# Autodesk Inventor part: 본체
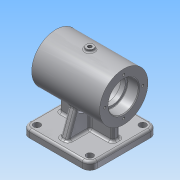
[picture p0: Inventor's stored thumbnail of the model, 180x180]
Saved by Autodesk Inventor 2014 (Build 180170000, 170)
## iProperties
Created: 2019-06
Part Number: 본체
Material: 알루미늄 6061
Document SubType Name: Modeling
Designer: user
Density: 2.71 g/cm^3
Appearance: 알루미늄 - 평지
Mass: 688.176 g
Surface Area: 608.027 cm^2
Volume: 253.94 cm^3
Author: user
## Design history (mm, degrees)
sketch "스케치1"
  geometry: L1 (-45, 0)-(45, 0); L2 (-45, 0)-(-45, 32); L3 (-45, 32)-(45, 32); L4 (45, 32)-(45, 0); L5 (-45, 20)-(-30, 20); L6 (-30, 20)-(-30, 17); L7 (-30, 17)-(-24, 17); L8 (-24, 17)-(-24, 25); L9 (-24, 25)-(24, 25); L10 (24, 25)-(24, 17); L11 (24, 17)-(30, 17); L12 (30, 17)-(30, 20); L13 (30, 20)-(45, 20); 2 further points
  constraints: 26 end point, 7 parallel, 4 perpendicular, 2 point on line, 1 coincident, 1 collinear, 1 horizontal, 1 midpoint
  dimensions: "d0" = 90 distance of L1.end L1.start; "d1" = 64 diameter of L3 L1; "d2" = 34 diameter of L7 L1; "d3" = 40 diameter of L5 L1; "d4" = 34 diameter of L11 L1; "d5" = 40 diameter of L13 L1; "d6" = 50 diameter of L9 L1; "d7" = 48 distance between parallel lines of L10 L8; "d8" = 15 distance between parallel lines of L6 L2; "d9" = 15 distance between parallel lines of L4 L12; "d10" = 6 distance between parallel lines of L8 L6; "d11" = 6 distance between parallel lines of L12 L10 (derived)
revolve "회전1" sketch "스케치1" stored, may be unused: angle "d12" = 90 deg
sketch "스케치2"
  geometry: L1 (-45, -55)-(45, -55); L2 (45, -55)-(45, -65); L3 (45, -65)-(-45, -65); L4 (-45, -65)-(-45, -55); 2 further points
  constraints: 8 end point, 2 parallel, 1 horizontal, 1 midpoint, 1 perpendicular, 1 vertical alignment
  dimensions: "d13" = 10 distance between parallel lines of L1 L3; "d14" = 90 distance between parallel lines of L2 L4; "d15" = 65 distance from line of L3 point (0, 0)
extrude "돌출1" join sketch "스케치2" stored distance "d16" = 90; taper "d17" = 0 deg
sketch "스케치3"
  geometry: L1 (40, -40)-(50, -40); L2 (50, -40)-(50, -50); L3 (50, -50)-(40, -50); L4 (40, -50)-(40, -40); L5 (40, -40)-(50, -50); L6 (50, -40)-(40, -50); 1 further point
  constraints: 12 end point, 2 midpoint, 2 parallel, 1 horizontal, 1 perpendicular
  dimensions: "d18" = 10 distance of L2.end L3.end; "d19" = 10 distance of L1.end L2.end
extrude "돌출2" join sketch "스케치3" stored distance "d20" = 90; taper "d21" = 0 deg
sketch "스케치4"
  geometry: L1 (24, 25)-(-24, 25) reference; L2 (-24, 25)-(-24, 17) reference; L3 (-24, 17)-(-30, 17) reference; L4 (-30, 17)-(-30, 20) reference; L5 (-30, 20)-(-45, 20) reference; L6 (-45, 20)-(-45, 32) reference; L7 (-45, 32)-(45, 32) reference; L8 (45, 32)-(45, 20) reference; L9 (45, 20)-(30, 20) reference; L10 (30, 20)-(30, 17) reference; L11 (30, 17)-(24, 17) reference; L12 (24, 17)-(24, 25) reference; L13 (-24, -25)-(24, -25) reference; L14 (24, -25)-(24, -17) reference; L15 (24, -17)-(30, -17) reference; L16 (30, -17)-(30, -20) reference; L17 (30, -20)-(45, -20) reference; L18 (45, -20)-(45, -32) reference; L19 (45, -32)-(5, -32) reference; L20 (5, -32)-(5, -55) reference; L21 (5, -55)-(45, -55) reference; L22 (45, -55)-(45, -65) reference; L23 (45, -65)-(-45, -65) reference; L24 (-45, -65)-(-45, -55) reference; L25 (-45, -55)-(-5, -55) reference; L26 (-5, -55)-(-5, -32) reference; L27 (-5, -32)-(-45, -32) reference; L28 (-45, -32)-(-45, -20) reference; L29 (-45, -20)-(-30, -20) reference; L30 (-30, -20)-(-30, -17) reference; L31 (-30, -17)-(-24, -17) reference; L32 (-24, -17)-(-24, -25) reference; L33 (-35, -32)-(-35, -55); L34 (35, -32)-(35, -55); 1 further point
  constraints: 4 end point, 4 point on line, 2 parallel
  dimensions: "d22" = 35 distance from line of L33 point (0, 0); "d23" = 35 distance from line of L34 point (0, 0)
feature "리브1" sketch "스케치4" dims "d24" = 1, "d25" = 10, "d26" = 0, "d27" = 0, "d28" = 1, "d29" = 1
sketch "스케치5"
  geometry: L1 (-45, -55)-(-5, -55) reference; L2 (-5, -55)-(-5, -31.607) reference; L3 (5, -31.607)-(5, -55) reference; L4 (5, -55)-(45, -55) reference; L5 (45, -55)-(45, -65) reference; L6 (45, -65)-(-45, -65) reference; L7 (-45, -65)-(-45, -55) reference; L8 (-23.058, -22.189)-(-35, -55); L9 (23.058, -22.189)-(35, -55); C1 r 25 at (0, 0) reference; A1 r 32 centre (0, 0) between (5, -31.607) and (-5, -31.607) reference; 1 further point
  constraints: 4 end point, 2 point on circle, 2 point on line
  dimensions: "d30" = 10 distance from line of L7 L8.end; "d31" = 10 distance from line of L5 L9.end; "d32" = 110 deg angle of L1 L8; "d33" = 110 deg angle of L4 L9
feature "리브2" sketch "스케치5" dims "d34" = 1, "d35" = 10, "d36" = 0, "d37" = 0, "d38" = 1, "d39" = 1
fillet "모깎기1" dims "d40" = 10
sketch "스케치6"
  geometry: L1 (-5, -5)-(75, -85); L2 (75, -5)-(-5, -85); C1 r 4.5 at (0, -10); C2 r 4.5 at (0, -80); C3 r 4.5 at (70, -10); C4 r 4.5 at (70, -80); A1 r 10 centre (70, -80) between (70, -90) and (80, -80) reference; A2 r 10 centre (70, -10) between (80, -10) and (70, 0) reference; A3 r 10 centre (0, -10) between (0, 0) and (-10, -10) reference; A4 r 10 centre (0, -80) between (-10, -80) and (0, -90) reference; 1 further point
  constraints: 4 centre point, 4 coincident, 4 end point, 2 midpoint
  dimensions: "d42" = 9 diameter of C1; "d43" = 9 diameter of C2; "d44" = 9 diameter of C3; "d45" = 9 diameter of C4
extrude "돌출3" cut sketch "스케치6" stored distance "d52" = 90; taper "d53" = 0 deg
chamfer "모따기1" distance "d61" = 1; stored, may be unused: second distance "d62" = 2, angle "d63" = 45 deg
fillet "모깎기2" dims "d64" = 3
fillet "모깎기3" dims "d65" = 0.6
node "작업 평면1"
sketch "스케치9"
  geometry: C1 r 5 at (0, 0); 1 further point
  constraints: 1 centre point, 1 coincident
  dimensions: "d67" = 10 diameter of C1
extrude "돌출4" join sketch "스케치9" stored distance "d68" = 5; taper "d69" = 0 deg
sketch "스케치10"
  geometry: C1 r 5 at (0, 0) reference; 1 further point
  constraints: 1 coincident
hole "구멍1" sketch "스케치10" at (0, 0) diameter "d70" = 4.917; stored, may be unused: countersink angle "d74" = 90 deg, drill point angle "d76" = 118 deg; dims "d71" = 6, "d72" = 4, "d73" = 2, "d75" = 8
fillet "모깎기4" dims "d77" = 3
fillet "모깎기5" dims "d78" = 3
fillet "모깎기6" dims "d79" = 3
fillet "모깎기7" dims "d80" = 3
sketch "스케치11"
  geometry: L1 (0, 0)-(25, 0); C1 r 21 at (0, 0) reference; 1 further point
  constraints: 2 end point, 1 coincident, 1 horizontal
  dimensions: "d81" = 25 distance of L1.start L1.end
hole "구멍2" sketch "스케치11" at (25, 0) diameter "d82" = 3.242; stored, may be unused: countersink angle "d86" = 90 deg, drill point angle "d88" = 118 deg; dims "d83" = 7, "d84" = 4, "d85" = 2, "d87" = 9
sketch "스케치12"
  geometry: L1 (35, 65)-(-35, 65) reference; L2 (45, 58)-(45, 65) reference; 2 further points
  constraints: 1 other
  dimensions: "d92" = 45 distance from line of L2 point (0, 61); "d93" = 4 distance from line of point (0, 61) L1
feature "엠보싱1" sketch "스케치12" dims "d13" = 10, "d94" = 0.5, "d95" = 0
fillet "모깎기8" dims "d96" = 2
sketch "스케치14"
  geometry: L1 (0, 0)-(70, 0) reference; L2 (10, -5)-(60, -5); L3 (75, -5)-(75, -70); L4 (60, -85)-(10, -85); L5 (-5, -70)-(-5, -20); L6 (-5, -5)-(75, -85); L7 (75, -5)-(-5, -85); L8 (10, -10)-(10, -5); L9 (0, -20)-(-5, -20); L10 (60, -10)-(60, -5); L11 (70, -20)-(75, -20); L12 (0, -70)-(-5, -70); L13 (10, -80)-(10, -85); L14 (70, -70)-(75, -70); L15 (60, -80)-(60, -85); A1 r 10 centre (70, -80) between (70, -90) and (80, -80) reference; A2 r 10 centre (70, -10) between (80, -10) and (70, 0) reference; A3 r 10 centre (0, -10) between (0, 0) and (-10, -10) reference; A4 r 10 centre (0, -80) between (-10, -80) and (0, -90) reference; A5 r 10 centre (0, -10) between (0, -20) and (10, -10); A6 r 10 centre (70, -10) between (60, -10) and (70, -20); A7 r 10 centre (0, -80) between (10, -80) and (0, -70); A8 r 10 centre (70, -80) between (70, -70) and (60, -80); 1 further point
  constraints: 29 end point, 8 point on circle, 8 tangent, 6 perpendicular, 5 parallel, 4 centre point, 4 coincident, 2 midpoint, 1 horizontal, 1 point on line
  dimensions: "d99" = 80 distance of L6.end L7.end; "d100" = 80 distance of L3.start L6.end
extrude "돌출5" cut sketch "스케치14" distance "d106" = 5; taper "d107" = 0 deg
fillet "모깎기9" dims "d108" = 3
node "솔리드1"
mirror "대칭1"
mirror "대칭2"
pattern_circular "원형 패턴1" dims angle "d90" = 360 deg
mirror "대칭3"
node "절단 모서리 투영1"
node "절단 모서리 투영2"
other parameters: "d66" = 35, "d102" = 10, "d103" = 10
